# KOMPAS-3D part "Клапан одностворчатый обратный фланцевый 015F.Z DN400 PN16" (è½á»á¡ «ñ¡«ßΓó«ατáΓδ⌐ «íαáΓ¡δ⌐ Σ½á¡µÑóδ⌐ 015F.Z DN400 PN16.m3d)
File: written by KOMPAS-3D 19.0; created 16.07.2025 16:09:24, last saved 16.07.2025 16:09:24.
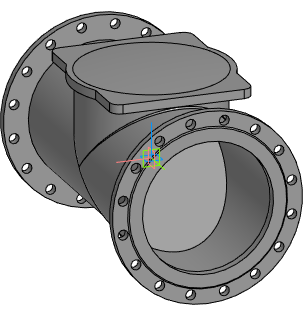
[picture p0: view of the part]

Document properties: Полное имя файла: E:\Dendor Работа Сачек\3D для проектировщиков\5.4 Тип 015F.Z. Клапан одностворчатый обратный фланцевый\stp_Клапан одностворчатый обратный фланцевый 015F.Z PN10_16\Клапан одностворчатый обратный фланцевый 015F.Z DN400 PN16.m3d

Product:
- Part/product: Клапан одностворчатый обратный фланцевый 015F.Z DN400 PN16

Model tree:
1. Операция без истории:1  (labels: Клапан одностворчатый обратный фланцевый 015F.Z DN400 PN16)
2. Операция без истории:2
